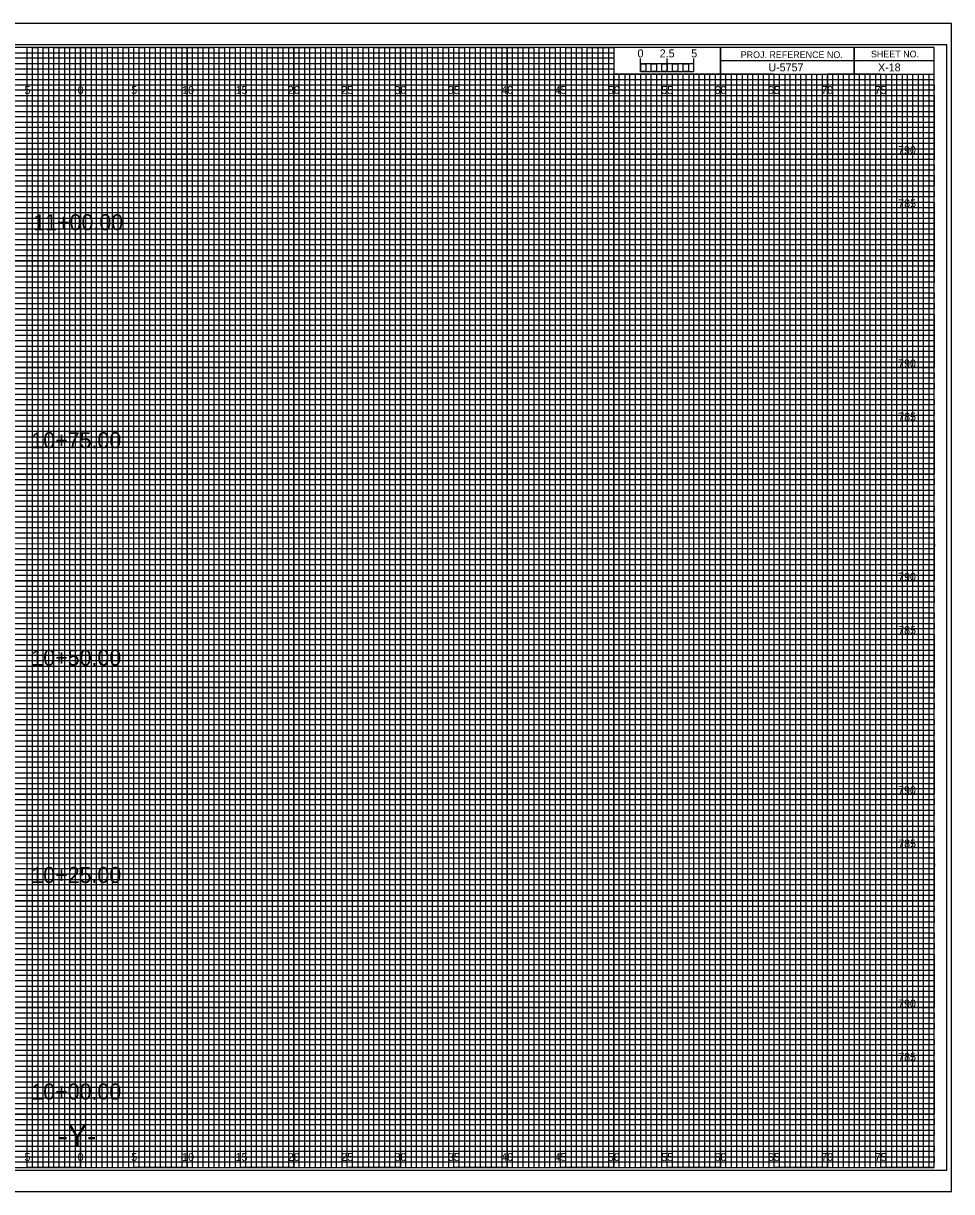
# Model space of a CAD drawing. Extents: x -7 to 162, y -2 to 107.
# Drawn here: x 74.6 to 161.7, y -2.3 to 107.3 of the extents above; entities that cross this region are included whole.
import ezdxf

# ---------------------------------------------------------------- set-up
doc = ezdxf.new("R2010")
doc.units = 0
for name, color, linetype in [('Prop XS Alignment Label', 7, 'Continuous'), ('Prop XS Bar Scale Labels', 7, 'Continuous'), ('Prop XS Elevation Labels', 7, 'Continuous'), ('Prop XS Offset Labels', 7, 'Continuous'), ('Prop XS Project Number', 7, 'Continuous'), ('Prop XS Sheet Number', 7, 'Continuous'), ('Prop XS Station Labels', 7, 'Continuous'), ('Sheet Cross Section CELL', 7, 'Continuous'), ('Sheet Cross Section Grid Major CELL', 7, 'Continuous'), ('Sheet Cross Section Grid Middle CELL', 7, 'Continuous'), ('Sheet Cross Section Grid Minor 1 CELL', 7, 'Continuous'), ('Sheet Cross Section Grid Minor 2 CELL', 7, 'Continuous'), ('Sheet Cross Section Scale CELL', 7, 'Continuous'), ('Sheet Cutting Line CELL', 7, 'Continuous'), ('Sheet DOT Grid CELL', 7, 'Continuous'), ('Sheet Plot Border Inside CELL', 7, 'Continuous'), ('Sheet Plot Border Outside CELL', 7, 'Continuous')]:
    doc.layers.add(name, color=color, linetype=linetype)

msp = doc.modelspace()

# ---------------------------------------------------------------- linework, layer by layer
at = {"layer": 'Sheet Cross Section CELL'}
for p, q in [((152.5, 105), (152.5, 102.5)), ((152.5, 102.5), (152.5, 105)), ((160, 103.75), (140, 103.75)), ((140, 103.75), (140, 102.5)), ((140, 102.5), (160, 102.5))]:
    msp.add_line(p, q, dxfattribs=at)
for points in [[(160, 105), (0, 105), (0, 0), (160, 0)], [(140, 105), (130, 105), (130, 102.52), (140, 102.52)], [(160, 105), (140, 105), (140, 102.5), (160, 102.5)]]:
    msp.add_lwpolyline(points, close=True, dxfattribs=at)
at = {"layer": 'Sheet Cross Section Grid Major CELL'}
for p, q in [((75, 105), (70, 105)), ((75, 0), (75, 105)), ((85, 105), (80, 105)), ((80, 105), (80, 0)), ((85, 0), (85, 105)), ((95, 105), (90, 105)), ((90, 105), (90, 0)), ((95, 0), (95, 105)), ((105, 105), (100, 105)), ((100, 105), (100, 0)), ((105, 0), (105, 105)), ((115, 105), (110, 105)), ((110, 105), (110, 0)), ((115, 0), (115, 105)), ((125, 105), (120, 105)), ((120, 105), (120, 0)), ((125, 0), (125, 105)), ((130, 105), (130, 0)), ((135, 0), (135, 102.5)), ((145, 102.5), (140, 102.5)), ((140, 102.5), (140, 0)), ((145, 0), (145, 102.5)), ((155, 102.5), (150, 102.5)), ((150, 102.5), (150, 0)), ((155, 0), (155, 102.5)), ((80, 0), (75, 0)), ((90, 0), (85, 0)), ((100, 0), (95, 0)), ((110, 0), (105, 0)), ((120, 0), (115, 0)), ((130, 0), (125, 0)), ((140, 0), (135, 0)), ((150, 0), (145, 0)), ((160, 0), (155, 0)), ((160, 0), (160, 0))]:
    msp.add_line(p, q, dxfattribs=at)
for points in [[(0, 100), (160, 100), (160, 95), (0, 95)], [(0, 90), (160, 90), (160, 85), (0, 85)], [(0, 80), (160, 80), (160, 75), (0, 75)], [(0, 70), (160, 70), (160, 65), (0, 65)], [(0, 60), (160, 60), (160, 55), (0, 55)], [(0, 50), (160, 50), (160, 45), (0, 45)], [(0, 40), (160, 40), (160, 35), (0, 35)], [(0, 30), (160, 30), (160, 25), (0, 25)], [(0, 20), (160, 20), (160, 15), (0, 15)], [(0, 10), (160, 10), (160, 5), (0, 5)]]:
    msp.add_lwpolyline(points, dxfattribs=at)
at = {"layer": 'Sheet Cross Section Grid Middle CELL'}
for points in [[(72.5, 0), (77.5, 0), (77.5, 105), (82.5, 105), (82.5, 0), (87.5, 0), (87.5, 105), (92.5, 105), (92.5, 0), (97.5, 0), (97.5, 105), (102.5, 105), (102.5, 0), (107.5, 0), (107.5, 105), (112.5, 105), (112.5, 0), (117.5, 0), (117.5, 105), (122.5, 105), (122.5, 0), (127.5, 0), (127.5, 105), (129.97, 105), (130, 105), (130, 102.5), (132.5, 102.5), (132.5, 0), (137.5, 0), (137.5, 102.5), (142.5, 102.5), (142.5, 0), (147.5, 0), (147.5, 102.5), (152.5, 102.5), (152.5, 0), (157.5, 0), (157.5, 102.5)], [(0, 102.5), (137.5, 102.5)], [(0, 92.5), (160, 92.5), (160, 97.5), (0, 97.5)], [(0, 82.5), (160, 82.5), (160, 87.5), (0, 87.5)], [(0, 72.5), (160, 72.5), (160, 77.5), (0, 77.5)], [(0, 62.5), (160, 62.5), (160, 67.5), (0, 67.5)], [(0, 52.5), (160, 52.5), (160, 57.5), (0, 57.5)], [(0, 42.5), (160, 42.5), (160, 47.5), (0, 47.5)], [(0, 32.5), (160, 32.5), (160, 37.5), (0, 37.5)], [(0, 22.5), (160, 22.5), (160, 27.5), (0, 27.5)], [(0, 12.5), (160, 12.5), (160, 17.5), (0, 17.5)], [(0, 2.5), (160, 2.5), (160, 7.5), (0, 7.5)]]:
    msp.add_lwpolyline(points, dxfattribs=at)
at = {"layer": 'Sheet Cross Section Grid Minor 1 CELL'}
for p, q in [((0, 104.5), (130, 104.5)), ((130, 104.5), (130, 103.99)), ((130, 103.99), (0, 103.99)), ((0, 103.5), (130, 103.5)), ((130, 102.95), (0, 102.95)), ((130, 103.5), (130, 102.95)), ((0, 102), (160, 102))]:
    msp.add_line(p, q, dxfattribs=at)
for points in [[(0, 101.5), (135, 101.5), (160, 101.5), (160, 101), (0, 101)], [(0, 100.5), (160, 100.5), (160, 99.5), (0, 99.5)], [(0, 99), (160, 99), (160, 98.5), (0, 98.49)], [(0, 98), (160, 98), (160, 97), (0, 97)], [(0, 96.5), (160, 96.5), (160, 96), (0, 96)], [(0, 95.5), (160, 95.5), (160, 94.5), (0, 94.5)], [(0, 94), (160, 94), (160, 93.5), (0, 93.5)], [(0, 93), (160, 93), (160, 92), (0, 92)], [(0, 91.5), (160, 91.5), (160, 91), (0, 91)], [(0, 90.5), (160, 90.5), (160, 89.5), (0, 89.5)], [(0, 89), (160, 89), (160, 88.5), (0, 88.5)], [(0, 88), (160, 88), (160, 86.98), (160, 86.5), (160, 86), (0, 86)], [(0, 87), (160, 87), (160, 86.5), (0, 86.5)], [(0, 85.5), (160, 85.5), (160, 84.5), (0, 84.52)], [(0, 84.52), (160, 84.5), (160, 84), (0, 84)], [(0, 83.5), (160, 83.5), (160, 83), (0, 83)], [(0, 82), (160, 82), (160, 81.5), (0, 81.5)], [(0, 81), (160, 81), (160, 80.5), (0, 80.5)], [(-0.04, 79.45), (160, 79.45), (160, 78.94), (-0.04, 78.94)], [(0, 78.5), (160, 78.5), (160, 78), (0, 78)], [(0, 77), (160, 77), (160, 76.5), (0, 76.5)], [(0, 76), (160, 76), (160, 75.5), (0, 75.5)], [(0, 74.5), (160, 74.5), (160, 74), (0, 74)], [(0, 73.5), (160, 73.5), (160, 73), (0, 73)], [(0, 72), (160, 72), (160, 71.5), (0, 71.5)], [(0, 71), (160, 71), (160, 70.5), (0, 70.5)], [(0, 69.5), (160, 69.5), (160, 68.99), (0, 69)], [(0, 68.5), (160, 68.5), (160, 68), (0, 68)], [(0, 67), (160, 67), (160, 66.5), (0, 66.5)], [(0, 66), (160, 66), (160, 65.5), (0, 65.5)], [(0, 64.5), (160, 64.5), (160, 64), (0, 64)], [(0, 63.5), (160, 63.5), (160, 63), (0, 63)], [(0, 62), (160, 62), (160, 61.5), (0, 61.5)], [(0, 61), (160, 61), (160, 60.5), (0, 60.5)], [(0, 59.5), (160, 59.5), (160, 59), (0, 59)], [(0, 58.5), (160.03, 58.45), (160, 58), (0, 58)], [(0, 57), (160, 57), (160, 56.5), (0, 56.5)], [(0, 56), (160, 56), (160, 55.5), (0, 55.5)], [(0, 54.5), (160, 54.5), (160, 54), (0, 54)], [(0, 53.5), (160, 53.5), (160, 53), (0, 53)], [(0, 52), (160, 52), (160, 51.5), (0, 51.5)], [(0, 51), (160, 51), (160, 50.5), (0, 50.5)], [(0, 49.5), (160, 49.5), (160, 49), (0, 49)], [(0, 48.5), (160, 48.5), (160, 48), (0, 48)], [(0, 47), (160, 47), (160, 46.5), (0, 46.5)], [(0, 46), (160, 46), (160, 45.5), (0, 45.5)], [(0, 44.5), (160, 44.5), (160, 44), (0, 44)], [(0, 43.5), (160, 43.5), (160, 43), (0, 43)], [(0, 42), (160, 42), (160, 41.5), (0, 41.5)], [(0, 41), (160, 41), (160, 40.5), (0, 40.5)], [(0, 39.5), (160, 39.5), (160, 38.99), (0, 39)], [(0, 38.5), (160, 38.5), (160, 38), (0, 38)], [(0, 37), (160, 37), (160, 36.5), (0, 36.5)], [(0, 36), (160, 36), (160, 35.5), (0, 35.5)], [(0, 34.5), (160, 34.5), (160, 34), (0, 34)], [(0, 33.5), (160, 33.5), (160, 33), (0, 33)], [(0, 32), (160, 32), (160, 31.5), (0, 31.5)], [(0, 31), (160, 31), (160, 30.5), (0, 30.5)], [(0, 29.5), (160, 29.5), (160, 29), (0, 29)], [(0, 28.5), (160.03, 28.46), (160, 28), (0, 28)], [(0, 27), (160, 27), (160, 26.5), (0, 26.5)], [(0, 26), (160, 26), (160, 25.5), (0, 25.5)], [(0, 24.5), (160, 24.5), (160, 24), (0, 24)], [(0, 23.5), (160, 23.5), (160, 23), (0, 23)], [(0, 22), (160, 22), (160, 21.5), (0, 21.5)], [(0, 21), (160, 21), (160, 20.5), (0, 20.5)], [(0, 19.5), (160, 19.5), (160, 19), (0, 19)], [(0, 18.5), (160, 18.5), (160, 18), (0, 18)], [(0, 17), (160, 17), (160, 16.5), (0, 16.5)], [(0, 16), (160, 16), (160, 15.5), (0, 15.5)], [(0, 14.5), (160, 14.5), (160, 14), (0, 14)], [(0, 13.5), (160, 13.5), (160, 13), (0, 13)], [(0, 12), (160, 12), (160, 11.5), (0, 11.5)], [(0, 11), (160, 11), (160, 10.5), (0, 10.5)], [(0, 9.5), (160, 9.5), (160, 9), (0, 9)], [(0, 8.5), (160, 8.5), (160, 8), (0, 8)], [(0, 7), (160, 7), (160, 6.5), (0, 6.5)], [(0, 6), (160, 6), (160, 5.5), (0, 5.5)], [(0, 4.5), (160, 4.5), (160, 4), (0, 4)], [(0, 3.5), (160, 3.5), (160, 3), (0, 3)], [(0, 2), (160, 2), (160, 1.5), (0, 1.5)], [(0, 1), (160, 1), (160, 0.5), (0, 0.5)]]:
    msp.add_lwpolyline(points, dxfattribs=at)
at = {"layer": 'Sheet Cross Section Grid Minor 2 CELL'}
for p, q in [((133.5, 102.5), (133, 102.5)), ((133, 102.5), (133, 0)), ((133.5, 0), (133.5, 102.5)), ((134.5, 102.5), (134, 102.5)), ((134, 102.5), (134, 0)), ((134.5, 0), (134.5, 102.5)), ((133, 0), (132.5, 0)), ((134, 0), (133.5, 0))]:
    msp.add_line(p, q, dxfattribs=at)
for points in [[(75, 0), (75.5, 0), (75.5, 105), (76, 105), (76, 0)], [(76, 0), (76.5, 0), (76.5, 105), (77, 105), (77, 0)], [(77.5, 0), (78, 0), (78, 105), (78.5, 105), (78.5, 0)], [(78.5, 0), (79, 0), (79, 105), (79.5, 105), (79.5, 0)], [(80, 0), (80.5, 0), (80.5, 105), (81, 105), (81, 0)], [(81, 0), (81.5, 0), (81.5, 105), (82, 105), (82, 0)], [(82.5, 0), (83, 0), (83, 105), (83.5, 105), (83.5, 0)], [(83.5, 0), (84, 0), (84, 105), (84.5, 105), (84.5, 0)], [(85, 0), (85.5, 0), (85.5, 105), (86, 105), (86, 0)], [(86, 0), (86.5, 0), (86.5, 105), (87, 105), (87, 0)], [(87.5, 0), (88, 0), (88, 105), (88.5, 105), (88.5, 0)], [(88.5, 0), (89, 0), (89, 105), (89.5, 105), (89.5, 0)], [(90, 0), (90.5, 0), (90.5, 105), (91, 105), (91, 0)], [(91, 0), (91.5, 0), (91.5, 105), (92, 105), (92, 0)], [(92.5, 0), (93, 0), (93, 105), (93.5, 105), (93.5, 0)], [(93.5, 0), (94, 0), (94, 105), (94.5, 105), (94.5, 0)], [(95, 0), (95.5, 0), (95.5, 105), (96, 105), (96, 0)], [(96, 0), (96.5, 0), (96.5, 105), (97, 105), (97, 0)], [(97.5, 0), (98, 0), (98, 105), (98.5, 105), (98.5, 0)], [(98.5, 0), (99, 0), (99, 105), (99.5, 105), (99.5, 0)], [(100, 0), (100.5, 0), (100.5, 105), (101, 105), (101, 0)], [(101, 0), (101.5, 0), (101.5, 105), (102, 105), (102, 0)], [(102.5, 0), (103, 0), (103, 105), (103.5, 105), (103.5, 0)], [(103.5, 0), (104, 0), (104, 105), (104.5, 105), (104.5, 0)], [(105, 0), (105.5, 0), (105.5, 105), (106, 105), (106, 0)], [(106, 0), (106.5, 0), (106.5, 105), (107, 105), (107, 0)], [(107.5, 0), (108, 0), (108, 105), (108.5, 105), (108.5, 0)], [(108.5, 0), (109, 0), (109, 105), (109.5, 105), (109.5, 0)], [(110, 0), (110.5, 0), (110.5, 105), (111, 105), (111, 0)], [(111, 0), (111.5, 0), (111.5, 105), (112, 105), (112, 0)], [(112.5, 0), (113, 0), (113, 105), (113.5, 105), (113.5, 0)], [(113.5, 0), (114, 0), (114, 105), (114.5, 105), (114.5, 0)], [(115, 0), (115.5, 0), (115.5, 105), (116, 105), (116, 0)], [(116, 0), (116.5, 0), (116.5, 105), (117, 105), (117, 0)], [(117.5, 0), (118, 0), (118, 105), (118.5, 105), (118.5, 0)], [(118.5, 0), (119, 0), (119, 105), (119.5, 105), (119.5, 0)], [(120, 0), (120.5, 0), (120.5, 105), (121, 105), (121, 0)], [(121, 0), (121.5, 0), (121.5, 105), (122, 105), (122, 0)], [(122.5, 0), (123, 0), (123, 105), (123.5, 105), (123.5, 0)], [(123.5, 0), (124, 0), (124, 105), (124.5, 105), (124.5, 0)], [(125, 0), (125.5, 0), (125.5, 105), (126, 105), (126, 0)], [(126, 0), (126.5, 0), (126.5, 105), (127, 105), (127, 0)], [(127.5, 0), (128, 0), (128, 105), (128.5, 105), (128.5, 0)], [(128.5, 0), (129, 0), (129, 105), (129.5, 105), (129.5, 0)], [(130, 0), (130.5, 0), (130.5, 102.5), (131.01, 102.5), (131.01, 0)], [(131, 0), (131.5, 0), (131.5, 102.5), (132, 102.5), (132, 0)], [(135, 0), (135.49, 0), (135.49, 102.5), (136, 102.5), (136, 0)], [(136, 0), (136.5, 0), (136.5, 102.5), (137.03, 102.5), (137.03, 0)], [(137.5, 0), (138, 0), (138, 102.5), (138.5, 102.5), (138.5, 0)], [(138.5, 0), (139, 0), (139, 102.5), (139.5, 102.5), (139.5, 0)], [(140, 0), (140.5, 0), (140.5, 102.5), (141, 102.5), (141, 0)], [(141, 0), (141.5, 0), (141.5, 102.5), (142, 102.5), (142, 0)], [(142.5, 0), (143, 0), (143, 102.5), (143.5, 102.5), (143.5, 0)], [(143.5, 0), (144, 0), (144, 102.5), (144.5, 102.5), (144.5, 0)], [(145, 0), (145.5, 0), (145.5, 102.5), (146, 102.5), (146, 0)], [(146, 0), (146.5, 0), (146.5, 102.5), (147, 102.5), (147, 0)], [(147.5, 0), (148, 0), (148, 102.5), (148.5, 102.5), (148.5, 0)], [(148.5, 0), (149, 0), (149, 102.5), (149.5, 102.5), (149.5, 0)], [(150, 0), (150.5, 0), (150.5, 102.5), (151, 102.5), (151, 0)], [(151, 0), (151.5, 0), (151.5, 102.5), (152, 102.5), (152, 0)], [(152.5, 0), (153, 0), (153, 102.5), (153.5, 102.5), (153.5, 0)], [(153.5, 0), (154, 0), (154, 102.5), (154.5, 102.5), (154.5, 0)], [(155, 0), (155.5, 0), (155.5, 102.5), (156, 102.5), (156, 0)], [(156, 0), (156.5, 0), (156.5, 102.5), (157, 102.5), (157, 0)], [(157.5, 0), (158, 0), (158, 102.5), (158.5, 102.5), (158.5, 0)], [(158.5, 0), (159, 0), (159, 102.5), (159.5, 102.5), (159.5, 0)]]:
    msp.add_lwpolyline(points, dxfattribs=at)
at = {"layer": 'Sheet Cross Section Scale CELL'}
for p, q in [((132.5, 102.75), (132.5, 103.95)), ((132.5, 103.45), (132.5, 103.95)), ((135, 102.75), (135, 103.95)), ((137.5, 102.75), (137.5, 103.95)), ((137.5, 103.45), (137.5, 103.95))]:
    msp.add_line(p, q, dxfattribs=at)
for points in [[(137.5, 103.45), (132.5, 103.45), (132.5, 102.75), (137.5, 102.75)], [(132.5, 103.45), (133, 103.45), (133, 102.75), (132.5, 102.75)], [(133.5, 103.45), (134, 103.45), (134, 102.75), (133.5, 102.75)], [(134.5, 103.45), (135, 103.45), (135, 102.75), (134.5, 102.75)], [(135.5, 103.45), (136, 103.45), (136, 102.75), (135.5, 102.75)], [(136.5, 103.45), (137, 103.45), (137, 102.75), (136.5, 102.75)]]:
    msp.add_lwpolyline(points, close=True, dxfattribs=at)
at = {"layer": 'Sheet Cutting Line CELL'}
for p, q in [((161.65, 107.25), (-6.7, 107.25)), ((-6.7, -2.25), (161.65, -2.25))]:
    msp.add_line(p, q, dxfattribs=at)
at = {"layer": 'Sheet DOT Grid CELL'}
for p, q in [((75, 0), (75, 105)), ((80, 0), (80, 105)), ((85, 0), (85, 105)), ((90, 0), (90, 105)), ((95, 0), (95, 105)), ((100, 0), (100, 105)), ((105, 0), (105, 105)), ((110, 0), (110, 105)), ((115, 0), (115, 105)), ((120, 0), (120, 105)), ((125, 0), (125, 105)), ((130, 0), (130, 102.34)), ((135, 0), (135, 102.34)), ((140, 0), (140, 102.34)), ((145, 0), (145, 102.34)), ((150, 0), (150, 102.34)), ((155, 0), (155, 102.34)), ((0, 100), (160, 100)), ((0, 95), (160, 95)), ((0, 90), (160, 90)), ((0, 85), (160, 85)), ((0, 80), (160, 80)), ((0, 75), (160, 75)), ((0, 70), (160, 70)), ((0, 65), (160, 65)), ((0, 60), (160, 60)), ((0, 55), (160, 55)), ((0, 50), (160, 50)), ((0, 45), (160, 45)), ((0, 40), (160, 40)), ((0, 35), (160, 35)), ((0, 30), (160, 30)), ((0, 25), (160, 25)), ((0, 20), (160, 20)), ((0, 15), (160, 15)), ((0, 10), (160, 10)), ((0, 5), (160, 5))]:
    msp.add_line(p, q, dxfattribs=at)
at = {"layer": 'Sheet Plot Border Inside CELL'}
msp.add_lwpolyline([(-5.4, -0.25), (161.2, -0.25), (161.2, 105.25), (-5.4, 105.25)], close=True, dxfattribs=at)
at = {"layer": 'Sheet Plot Border Outside CELL'}
msp.add_lwpolyline([(-6.7, -2.25), (161.65, -2.25), (161.65, 107.25), (-6.7, 107.25)], close=True, dxfattribs=at)

# ---------------------------------------------------------------- texts
at = {"layer": 'Prop XS Alignment Label'}
msp.add_text('-Y-', height=2, dxfattribs=at).set_placement((77.92, 2))
at = {"layer": 'Prop XS Bar Scale Labels'}
for s, p in [('2.5', (134.29, 104.06)), ('5', (137.24, 104.06))]:
    msp.add_text(s, height=0.75, dxfattribs=at).set_placement(p)
at = {"layer": 'Prop XS Elevation Labels'}
for s, p in [('790', (156.63, 95)), ('785', (156.64, 90)), ('790', (156.63, 75)), ('785', (156.64, 70)), ('790', (156.63, 55)), ('785', (156.64, 50)), ('790', (156.63, 35)), ('785', (156.64, 30)), ('790', (156.63, 15)), ('785', (156.64, 10))]:
    msp.add_text(s, height=0.75, dxfattribs=at).set_placement(p)
at = {"layer": 'Prop XS Offset Labels'}
for s, p in [('5', (74.74, 100.62)), ('0', (79.73, 100.62)), ('0', (79.73, 100.62)), ('5', (84.74, 100.62)), ('10', (89.52, 100.62)), ('15', (94.53, 100.62)), ('20', (99.43, 100.62)), ('25', (104.44, 100.62)), ('30', (109.43, 100.62)), ('35', (114.44, 100.62)), ('40', (119.43, 100.62)), ('45', (124.44, 100.62)), ('50', (129.43, 100.62)), ('55', (134.44, 100.62)), ('60', (139.43, 100.62)), ('65', (144.44, 100.62)), ('70', (149.43, 100.62)), ('75', (154.44, 100.62)), ('5', (74.74, 0.62)), ('0', (79.73, 0.62)), ('0', (79.73, 0.62)), ('5', (84.74, 0.62)), ('10', (89.52, 0.62)), ('15', (94.53, 0.62)), ('20', (99.43, 0.62)), ('25', (104.44, 0.62)), ('30', (109.43, 0.62)), ('35', (114.44, 0.62)), ('40', (119.43, 0.62)), ('45', (124.44, 0.62)), ('50', (129.43, 0.62)), ('55', (134.44, 0.62)), ('60', (139.43, 0.62)), ('65', (144.44, 0.62)), ('70', (149.43, 0.62)), ('75', (154.44, 0.62))]:
    msp.add_text(s, height=0.75, dxfattribs=at).set_placement(p)
at = {"layer": 'Prop XS Project Number'}
msp.add_text('U-5757', height=0.75, dxfattribs=at).set_placement((144.47, 102.75))
at = {"layer": 'Prop XS Sheet Number'}
msp.add_text('X-18', height=0.75, dxfattribs=at).set_placement((154.75, 102.75))
at = {"layer": 'Prop XS Station Labels'}
for s, p in [('11+00.00', (75.57, 87.86)), ('10+75.00', (75.39, 67.43)), ('10+50.00', (75.39, 47.05)), ('10+25.00', (75.39, 26.68)), ('10+00.00', (75.39, 6.38))]:
    msp.add_text(s, height=1.5, dxfattribs=at).set_placement(p)
at = {"layer": 'Sheet Cross Section CELL'}
for s, p in [('PROJ. REFERENCE NO.', (141.88, 104)), ('SHEET NO.', (154.09, 104.06))]:
    msp.add_text(s, height=0.625, dxfattribs=at).set_placement(p)
at = {"layer": 'Sheet Cross Section Scale CELL'}
msp.add_text('0', height=0.75, dxfattribs=at).set_placement((132.21, 104.06))

doc.saveas('drawing.dxf')
